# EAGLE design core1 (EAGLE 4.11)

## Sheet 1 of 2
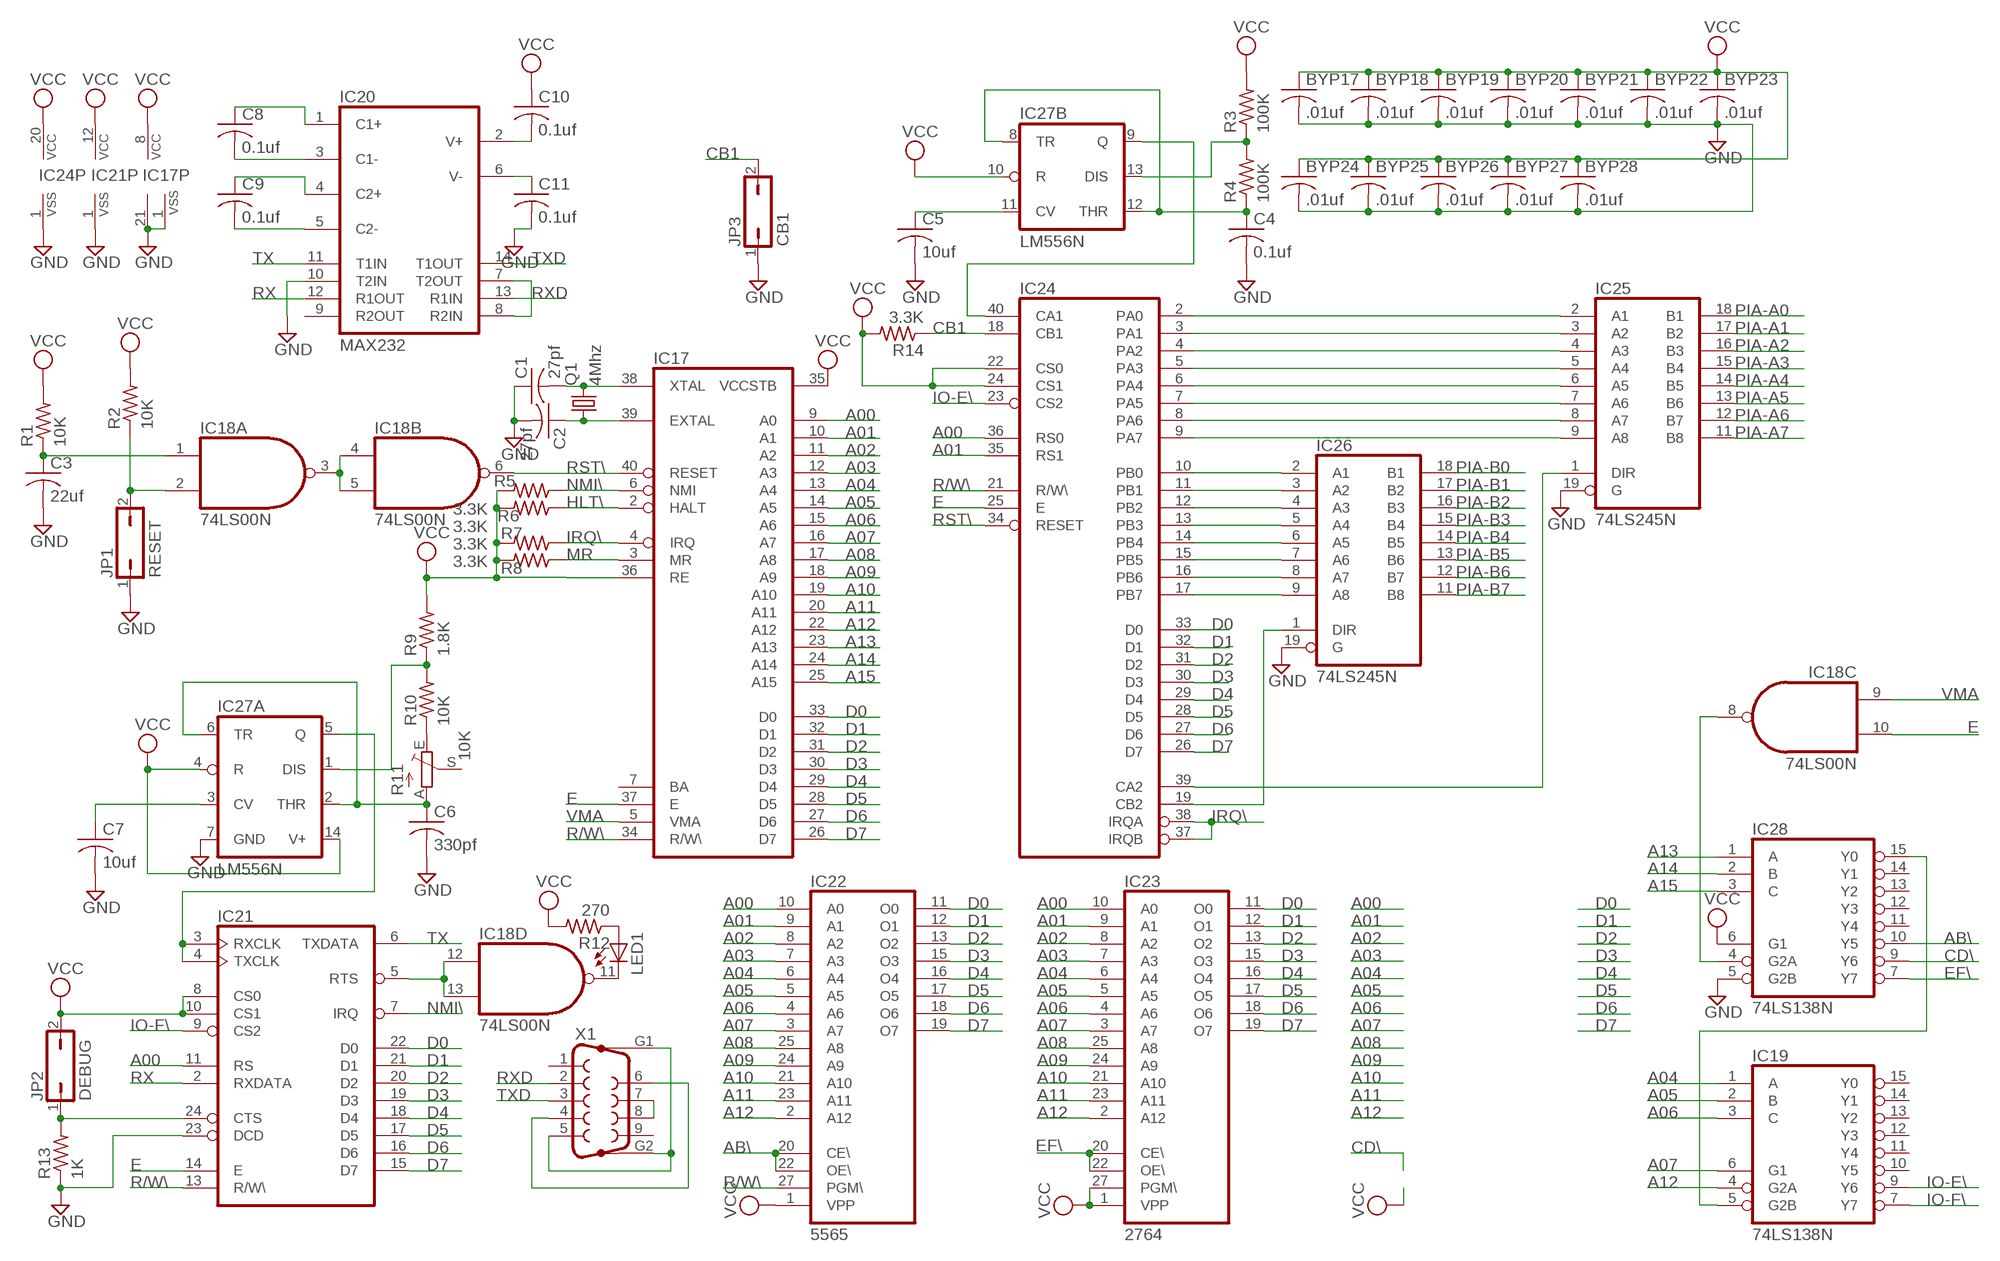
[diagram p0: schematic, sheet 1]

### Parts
BYP17  .01uf  C-US050-025X075  [C050-025X075]
BYP18  .01uf  C-US050-025X075  [C050-025X075]
BYP19  .01uf  C-US050-025X075  [C050-025X075]
BYP20  .01uf  C-US050-025X075  [C050-025X075]
BYP21  .01uf  C-US050-025X075  [C050-025X075]
BYP22  .01uf  C-US050-025X075  [C050-025X075]
BYP23  .01uf  C-US050-025X075  [C050-025X075]
BYP24  .01uf  C-US050-025X075  [C050-025X075]
BYP25  .01uf  C-US050-025X075  [C050-025X075]
BYP26  .01uf  C-US050-025X075  [C050-025X075]
BYP27  .01uf  C-US050-025X075  [C050-025X075]
BYP28  .01uf  C-US050-025X075  [C050-025X075]
C1  27pf  C-US050-025X075  [C050-025X075]
C2  27pf  C-US050-025X075  [C050-025X075]
C3  22uf  C-US102-043X133  [C102-043X133]
C4  0.1uf  C-US050-025X075  [C050-025X075]
C5  10uf  C-US050-025X075  [C050-025X075]
C6  330pf  C-US050-025X075  [C050-025X075]
C7  10uf  C-US050-025X075  [C050-025X075]
C8  0.1uf  C-US050-025X075  [C050-025X075]
C9  0.1uf  C-US050-025X075  [C050-025X075]
C10  0.1uf  C-US050-025X075  [C050-025X075]
C11  0.1uf  C-US050-025X075  [C050-025X075]
IC17  6802  [DIL40]
IC18  74LS00N  [DIL14]
IC19  74LS138N  [DIL16]
IC20  MAX232  [DIL16]
IC21  6850  [DIL24]
IC22  5565  2764  [DIL28]
IC23  2764  [DIL28]
IC24  6821  [DIL40]
IC25  74LS245N  [DIL20]
IC26  74LS245N  [DIL20]
IC27  LM556N  [DIL14]
IC28  74LS138N  [DIL16]
JP1  RESET  JP1Q  [JP1]
JP2  DEBUG  JP1Q  [JP1]
JP3  CB1  JP1Q  [JP1]
LED1  LED3MM  [LED3MM]
Q1  4Mhz  CRYTALHC18U-V  [HC18U-V]
R1  10K  R-US_0207/7  [0207/7]
R2  10K  R-US_0207/7  [0207/7]
R3  100K  R-US_0207/7  [0207/7]
R4  100K  R-US_0207/7  [0207/7]
R5  3.3K  R-US_0207/7  [0207/7]
R6  3.3K  R-US_0207/7  [0207/7]
R7  3.3K  R-US_0207/7  [0207/7]
R8  3.3K  R-US_0207/7  [0207/7]
R9  1.8K  R-US_0207/7  [0207/7]
R10  10K  R-US_0207/7  [0207/7]
R11  10K  TRIM_EU-B90P  [SP19L]
R12  270  R-US_0207/7  [0207/7]
R13  1K  R-US_0207/7  [0207/7]
R14  3.3K  R-US_0207/7  [0207/7]
X1  F09HP  [F09HP]

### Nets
A00: IC17.9(A0) IC21.11(RS) IC22.10(A0) IC23.10(A0) IC24.36(RS0)
A01: IC17.10(A1) IC22.9(A1) IC23.9(A1) IC24.35(RS1)
A02: IC17.11(A2) IC22.8(A2) IC23.8(A2)
A03: IC17.12(A3) IC22.7(A3) IC23.7(A3)
A04: IC17.13(A4) IC19.1(A) IC22.6(A4) IC23.6(A4)
A05: IC17.14(A5) IC19.2(B) IC22.5(A5) IC23.5(A5)
A06: IC17.15(A6) IC19.3(C) IC22.4(A6) IC23.4(A6)
A07: IC17.16(A7) IC19.6(G1) IC22.3(A7) IC23.3(A7)
A08: IC17.17(A8) IC22.25(A8) IC23.25(A8)
A09: IC17.18(A9) IC22.24(A9) IC23.24(A9)
A10: IC17.19(A10) IC22.21(A10) IC23.21(A10)
A11: IC17.20(A11) IC22.23(A11) IC23.23(A11)
A12: IC17.22(A12) IC19.4(G2A) IC22.2(A12) IC23.2(A12)
A13: IC17.23(A13) IC28.1(A)
A14: IC17.24(A14) IC28.2(B)
A15: IC17.25(A15) IC28.3(C)
AB\: IC22.20(CE\) IC22.22(OE\) IC28.10(Y5)
CB1: IC24.18(CB1) JP3.2 R14.1
CD\: IC28.9(Y6)
D0: IC17.33(D0) IC21.22(D0) IC22.11(O0) IC23.11(O0) IC24.33(D0)
D1: IC17.32(D1) IC21.21(D1) IC22.12(O1) IC23.12(O1) IC24.32(D1)
D2: IC17.31(D2) IC21.20(D2) IC22.13(O2) IC23.13(O2) IC24.31(D2)
D3: IC17.30(D3) IC21.19(D3) IC22.15(O3) IC23.15(O3) IC24.30(D3)
D4: IC17.29(D4) IC21.18(D4) IC22.16(O4) IC23.16(O4) IC24.29(D4)
D5: IC17.28(D5) IC21.17(D5) IC22.17(O5) IC23.17(O5) IC24.28(D5)
D6: IC17.27(D6) IC21.16(D6) IC22.18(O6) IC23.18(O6) IC24.27(D6)
D7: IC17.26(D7) IC21.15(D7) IC22.19(O7) IC23.19(O7) IC24.26(D7)
E: IC17.37(E) IC18.10(C:I1) IC21.14(E) IC24.25(E)
EF\: IC23.20(CE\) IC23.22(OE\) IC28.7(Y7)
GND [Power]: BYP17.2 BYP18.2 BYP19.2 BYP20.2 BYP21.2 BYP22.2 BYP23.2 BYP24.2 BYP25.2 BYP26.2 BYP27.2 BYP28.2 C1.1 C2.2 C3.2 C4.2 C5.2 C6.2 C7.2 C11.2 IC17.1(VSS) IC17.21(VSS) IC20.10(T2IN) IC21.1(VSS) IC21.23(DCD) IC24.1(VSS) IC25.19(G) IC26.19(G) IC27.7(A:GND) IC28.5(G2B) JP1.1 JP3.1 R13.1 ; also sheet 2
HLT\: IC17.2(HALT) R5.1
IO-E\: IC19.9(Y6) IC24.23(CS2)
IO-F\: IC19.7(Y7) IC21.9(CS2)
IRQ\: IC17.4(IRQ) IC24.37(IRQB) IC24.38(IRQA) R7.1
MR: IC17.3(MR) R8.1
N$3: C2.1 IC17.39(EXTAL) Q1.1
N$4: C1.2 IC17.38(XTAL) Q1.2
N$5: IC24.2(PA0) IC25.2(A1)
N$6: IC18.3(A:O) IC18.4(B:I0) IC18.5(B:I1)
N$21: C3.1 IC18.1(A:I0) R1.1
N$22: IC18.2(A:I1) JP1.2 R2.1
N$23: IC21.3(RXCLK) IC21.4(TXCLK) IC27.5(A:Q)
N$24: IC24.10(PB0) IC26.2(A1)
N$25: IC24.11(PB1) IC26.3(A2)
N$27: C6.1 IC27.2(A:THR) IC27.6(A:TR) R11.A
N$28: IC27.1(A:DIS) R9.1 R10.2
N$94: IC24.12(PB2) IC26.4(A3)
N$124: IC24.13(PB3) IC26.5(A4)
N$125: IC24.14(PB4) IC26.6(A5)
N$126: IC24.15(PB5) IC26.7(A6)
N$127: IC24.16(PB6) IC26.8(A7)
N$128: IC24.17(PB7) IC26.9(A8)
N$129: IC24.3(PA1) IC25.3(A2)
N$130: IC24.4(PA2) IC25.4(A3)
N$131: IC24.5(PA3) IC25.5(A4)
N$132: IC24.6(PA4) IC25.6(A5)
N$133: IC24.7(PA5) IC25.7(A6)
N$134: IC24.8(PA6) IC25.8(A7)
N$135: IC24.9(PA7) IC25.9(A8)
N$136: IC24.19(CB2) IC26.1(DIR)
N$137: IC24.39(CA2) IC25.1(DIR)
N$138: IC24.40(CA1) IC27.9(B:Q)
N$140: C4.1 IC27.8(B:TR) IC27.12(B:THR) R4.1
N$141: IC27.13(B:DIS) R3.1 R4.2
N$142: C5.1 IC27.11(B:CV)
N$143: R10.1 R11.E
N$144: X1.4 X1.6
N$145: X1.7 X1.8
N$146: X1.5 X1.G1 X1.G2
N$147: IC18.12(D:I0) IC18.13(D:I1) IC21.5(RTS)
N$148: IC18.11(D:O) LED1.K(C)
N$149: LED1.A R12.1
N$150: IC21.24(CTS) JP2.1 R13.2
N$151: IC18.8(C:O) IC28.4(G2A)
N$152: IC19.5(G2B) IC28.15(Y0)
N$153: IC20.7(T2OUT) IC20.8(R2IN)
N$154: C7.1 IC27.3(A:CV)
N$155: C9.2 IC20.5(C2-)
N$156: C9.1 IC20.4(C2+)
N$157: C8.2 IC20.3(C1-)
N$158: C8.1 IC20.1(C1+)
N$159: C11.1 IC20.6(V-)
N$160: C10.2 IC20.2(V+)
NMI\: IC17.6(NMI) IC21.7(IRQ) R6.1
PIA-A0: IC25.18(B1) ; also sheet 2
PIA-A1: IC25.17(B2) ; also sheet 2
PIA-A2: IC25.16(B3) ; also sheet 2
PIA-A3: IC25.15(B4) ; also sheet 2
PIA-A4: IC25.14(B5) ; also sheet 2
PIA-A5: IC25.13(B6) ; also sheet 2
PIA-A6: IC25.12(B7) ; also sheet 2
PIA-A7: IC25.11(B8) ; also sheet 2
PIA-B0: IC26.18(B1) ; also sheet 2
PIA-B1: IC26.17(B2) ; also sheet 2
PIA-B2: IC26.16(B3) ; also sheet 2
PIA-B3: IC26.15(B4) ; also sheet 2
PIA-B4: IC26.14(B5) ; also sheet 2
PIA-B5: IC26.13(B6) ; also sheet 2
PIA-B6: IC26.12(B7) ; also sheet 2
PIA-B7: IC26.11(B8) ; also sheet 2
R/W\: IC17.34(R/W\) IC21.13(R/W\) IC22.27(PGM\) IC24.21(R/W\)
RST\: IC17.40(RESET) IC18.6(B:O) IC24.34(RESET)
RX: IC20.12(R1OUT) IC21.2(RXDATA)
RXD: IC20.13(R1IN) X1.2
TX: IC20.11(T1IN) IC21.6(TXDATA)
TXD: IC20.14(T1OUT) X1.3
VCC [Power]: BYP17.1 BYP18.1 BYP19.1 BYP20.1 BYP21.1 BYP22.1 BYP23.1 BYP24.1 BYP25.1 BYP26.1 BYP27.1 BYP28.1 C10.1 IC17.8(VCC) IC17.35(VCCSTB) IC17.36(RE) IC21.8(CS0) IC21.10(CS1) IC21.12(VCC) IC22.1(VPP) IC23.1(VPP) IC23.27(PGM\) IC24.20(VCC) IC24.22(CS0) IC24.24(CS1) IC27.4(A:R) IC27.10(B:R) IC27.14(A:V+) IC28.6(G1) JP2.2 R1.2 R2.2 R3.2 R5.2 R6.2 R7.2 R8.2 R9.2 R12.2 R14.2 ; also sheet 2
VMA: IC17.5(VMA) IC18.9(C:I0)
Unconnected: IC17.7(BA) IC19.10(Y5) IC19.11(Y4) IC19.12(Y3) IC19.13(Y2) IC19.14(Y1) IC19.15(Y0) IC20.9(R2OUT) IC28.11(Y4) IC28.12(Y3) IC28.13(Y2) IC28.14(Y1) R11.S X1.1 X1.9

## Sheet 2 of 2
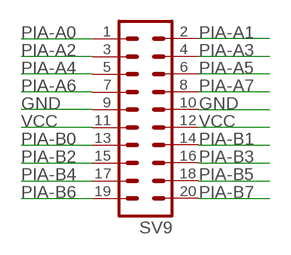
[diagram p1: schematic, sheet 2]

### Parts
SV9  MA10-2  [MA10-2]

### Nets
GND [Power]: SV9.9 SV9.10 ; also sheet 1
PIA-A0: SV9.1 ; also sheet 1
PIA-A1: SV9.2 ; also sheet 1
PIA-A2: SV9.3 ; also sheet 1
PIA-A3: SV9.4 ; also sheet 1
PIA-A4: SV9.5 ; also sheet 1
PIA-A5: SV9.6 ; also sheet 1
PIA-A6: SV9.7 ; also sheet 1
PIA-A7: SV9.8 ; also sheet 1
PIA-B0: SV9.13 ; also sheet 1
PIA-B1: SV9.14 ; also sheet 1
PIA-B2: SV9.15 ; also sheet 1
PIA-B3: SV9.16 ; also sheet 1
PIA-B4: SV9.17 ; also sheet 1
PIA-B5: SV9.18 ; also sheet 1
PIA-B6: SV9.19 ; also sheet 1
PIA-B7: SV9.20 ; also sheet 1
VCC [Power]: SV9.11 SV9.12 ; also sheet 1

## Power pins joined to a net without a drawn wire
GND: IC18.7(P:GND) IC19.8(GND) IC20.15(GND) IC22.14(GND) IC23.14(GND) IC25.10(GND) IC26.10(GND) IC28.8(GND)
VCC: IC18.14(P:VCC) IC19.16(VCC) IC20.16(VCC) IC22.28(VCC) IC23.28(VCC) IC25.20(VCC) IC26.20(VCC) IC28.16(VCC)

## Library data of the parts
BYP17-BYP28 C1-C11 = rcl:C-US: CAPACITOR, American symbol
IC17 = micro-motorola:6802: MICROCONTROLLER/MEMORY DEVICE
IC18 = 74xx-us:74*00: Quad 2-input NAND gate
IC19 IC28 = 74xx-us:74*138: 3-line to 8-line DECODER/DEMULTIPLEXER
IC20 = maxim:MAX232: RS232 TRANSEIVER
IC21 = micro-motorola:6850: MICROCONTROLLER/MEMORY DEVICE
IC22 IC23 = memory:2764: MEMORY
IC24 = micro-motorola:6821: MICROCONTROLLER/MEMORY DEVICE
IC25 IC26 = 74xx-us:74*245: Octal BUS TRANSCEIVER, 3-state
IC27 = linear:*556: Dual TIMER
JP1-JP3 = jumper:JP1Q: JUMPER
LED1 = led:LED: LED
Q1 = crystal:CRYTAL: CRYSTAL
R1-R10 R12-R14 = rcl:R-US_: RESISTOR, American symbol
R11 = pot:TRIM_EU-: POTENTIOMETER
SV9 = con-lstb:MA10-2: PIN HEADER
X1 = con-subd:F09HP: SUB-D

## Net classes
1 Power: width 0.508 mm, drill 0.254 mm, clearance 0.254 mm

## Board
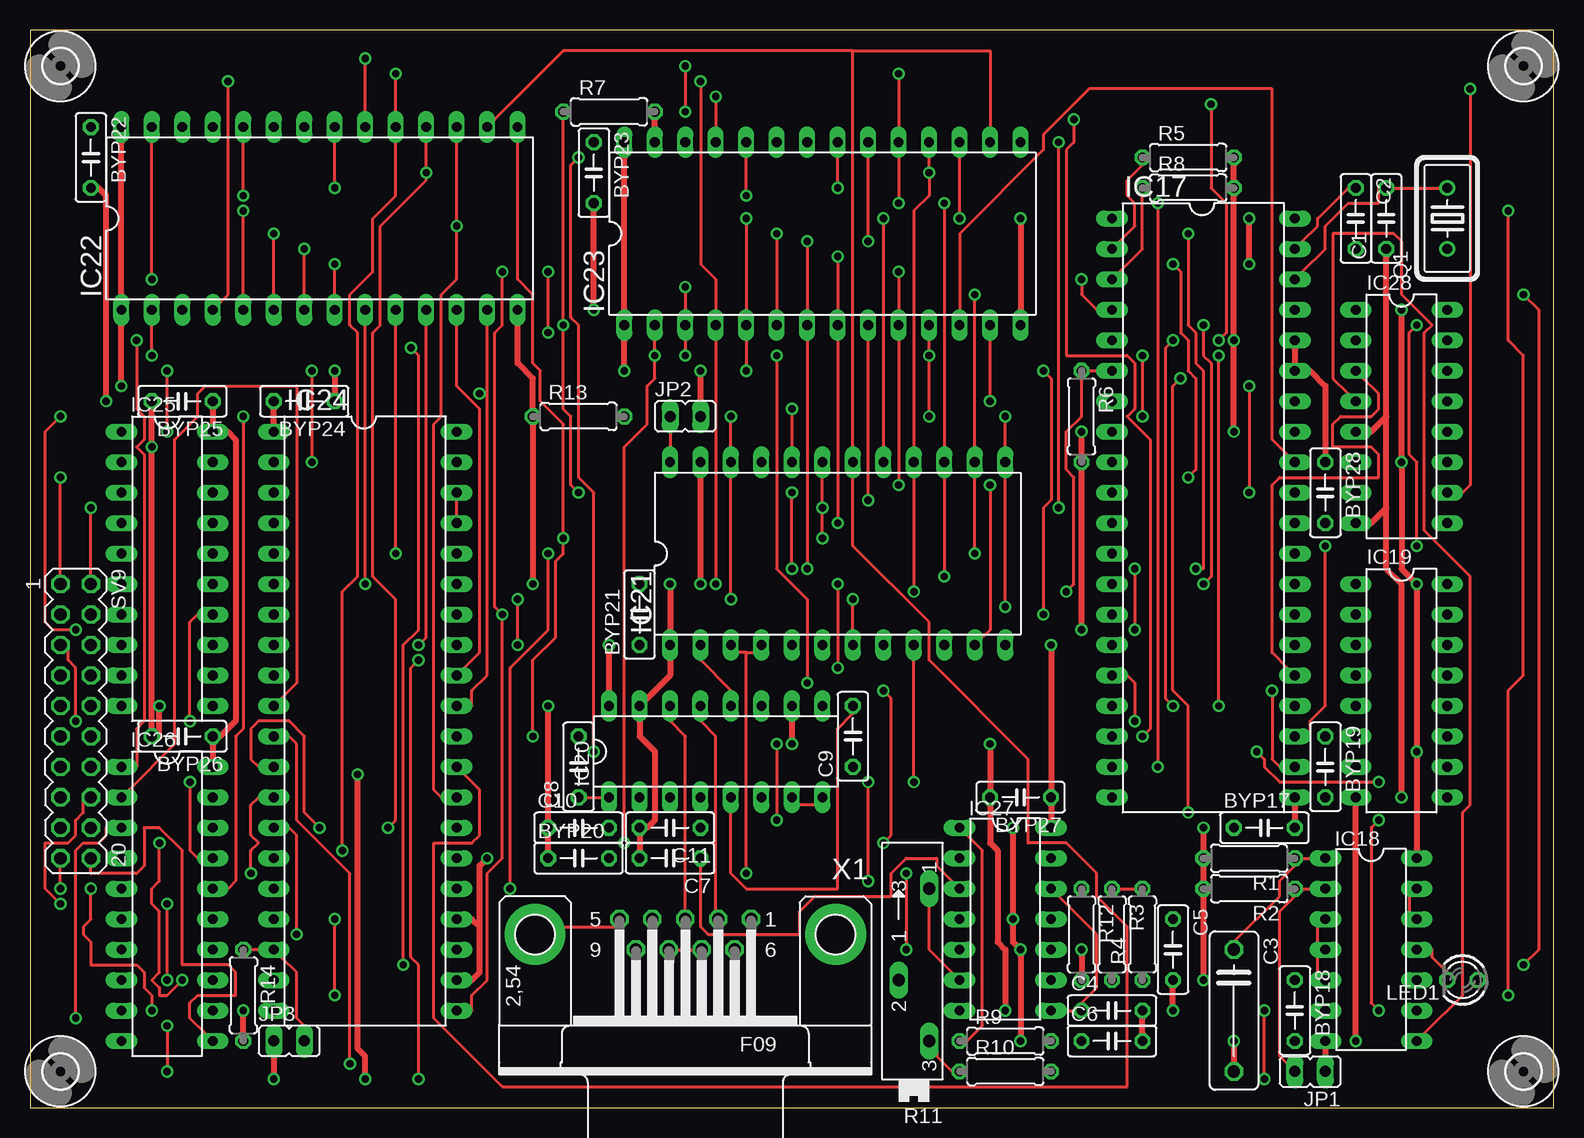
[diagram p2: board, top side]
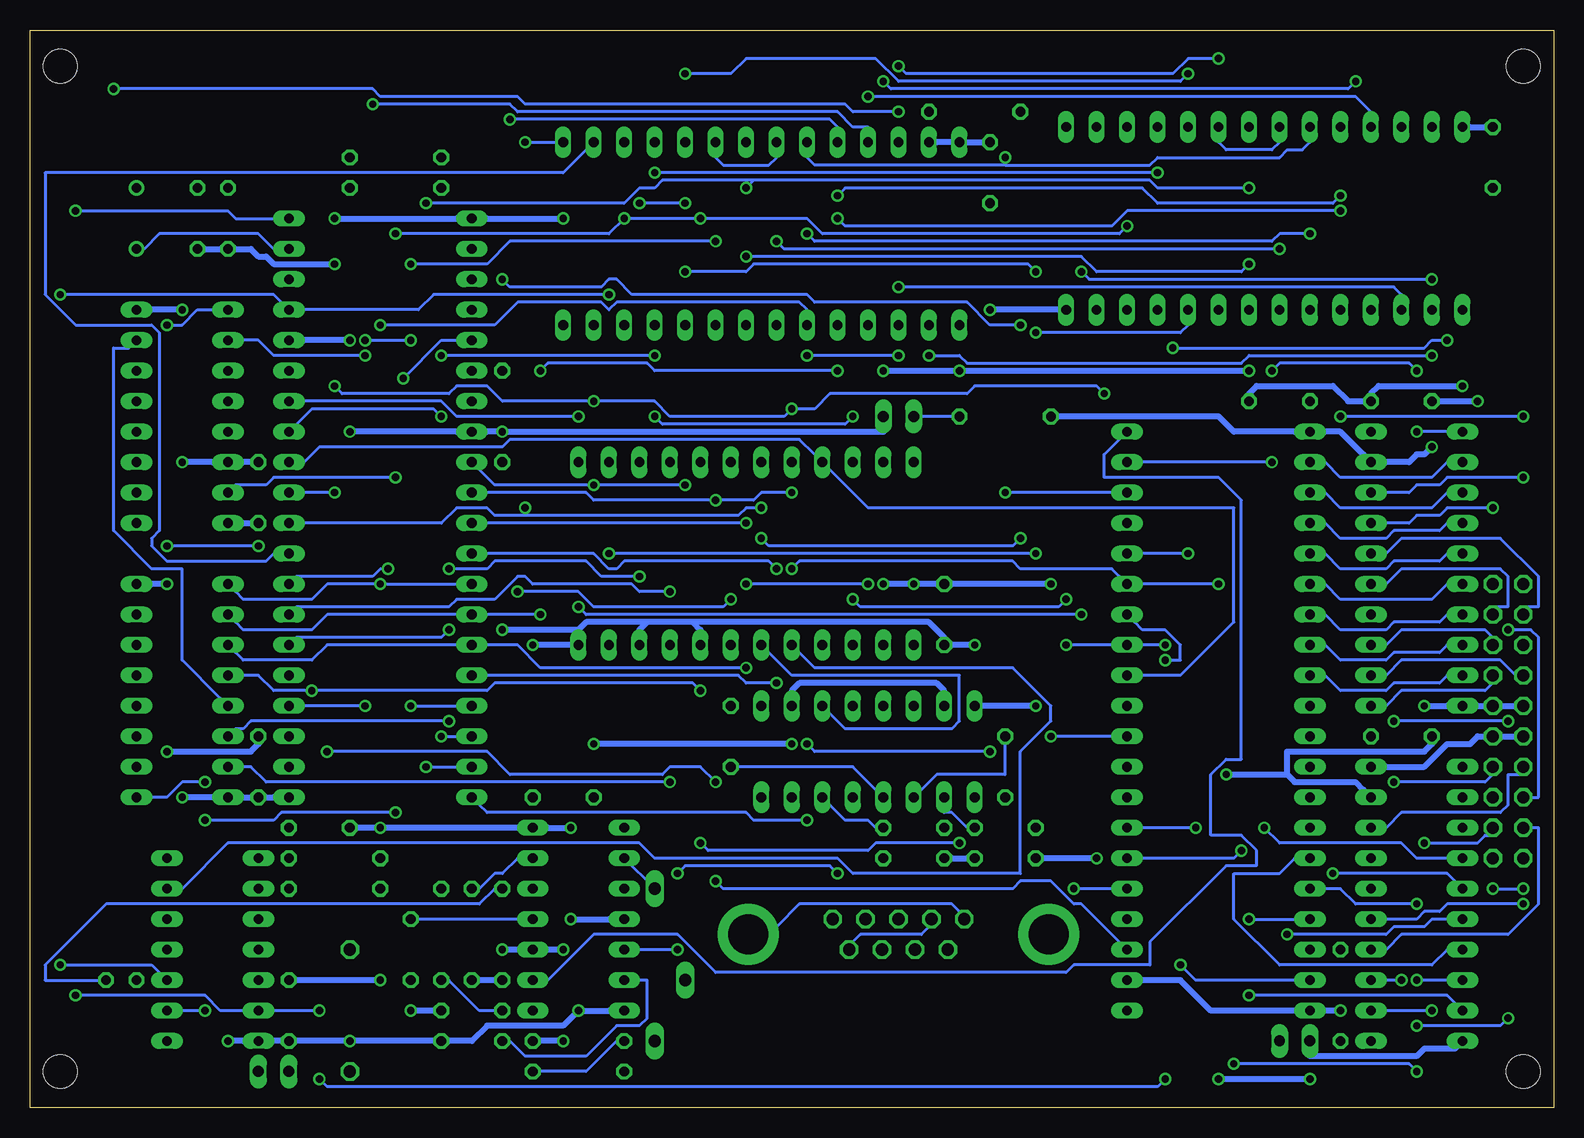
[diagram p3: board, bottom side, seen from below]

Size 126.98 x 89.84 mm. Coordinates in mm from the lower left corner, seen from the top.
Outline: 0,0 126.98,0 126.98,89.84 0,89.84 0,0
Copper layers (1*16): Top 0.035mm / dielectric 1.5mm / Bottom 0.035mm
Design rules "default": minimum track width 10mil, minimum drill 24mil, track to track 8mil, track to pad 8mil, pad to pad 8mil, via to via 8mil, smd to smd 8mil, copper to edge 40mil, drill to drill 8mil, minimum pad ring 10mil, minimum via ring 8mil, stop-mask expansion 4mil, vias tented up to drill 0mil, thermal gap 10mil

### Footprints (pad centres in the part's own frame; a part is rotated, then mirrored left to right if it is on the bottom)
C050-025X075 = drill 0.813 octagon: 1 -2.54,0; 2 2.54,0
C102-043X133 = drill 1.016 octagon: 1 -5.08,0; 2 5.08,0
DIL40 = drill 0.813 long: 1 -24.13,-7.62; 2 -21.59,-7.62; 3 -19.05,-7.62; 4 -16.51,-7.62; 5 -13.97,-7.62; 6 -11.43,-7.62; 7 -8.89,-7.62; 8 -6.35,-7.62; 9 -3.81,-7.62; 10 -1.27,-7.62; 11 1.27,-7.62; 12 3.81,-7.62; 13 6.35,-7.62; 14 8.89,-7.62; 15 11.43,-7.62; 16 13.97,-7.62; 17 16.51,-7.62; 18 19.05,-7.62; 19 21.59,-7.62; 20 24.13,-7.62; 21 24.13,7.62; 22 21.59,7.62; 23 19.05,7.62; 24 16.51,7.62; 25 13.97,7.62; 26 11.43,7.62; 27 8.89,7.62; 28 6.35,7.62; 29 3.81,7.62; 30 1.27,7.62; 31 -1.27,7.62; 32 -3.81,7.62; 33 -6.35,7.62; 34 -8.89,7.62; 35 -11.43,7.62; 36 -13.97,7.62; 37 -16.51,7.62; 38 -19.05,7.62; 39 -21.59,7.62; 40 -24.13,7.62
DIL14 = drill 0.813 long: 1 -7.62,-3.81; 2 -5.08,-3.81; 3 -2.54,-3.81; 4 0,-3.81; 5 2.54,-3.81; 6 5.08,-3.81; 7 7.62,-3.81; 8 7.62,3.81; 9 5.08,3.81; 10 2.54,3.81; 11 0,3.81; 12 -2.54,3.81; 13 -5.08,3.81; 14 -7.62,3.81
DIL16 = drill 0.813 long: 1 -8.89,-3.81; 2 -6.35,-3.81; 3 -3.81,-3.81; 4 -1.27,-3.81; 5 1.27,-3.81; 6 3.81,-3.81; 7 6.35,-3.81; 8 8.89,-3.81; 9 8.89,3.81; 10 6.35,3.81; 11 3.81,3.81; 12 1.27,3.81; 13 -1.27,3.81; 14 -3.81,3.81; 15 -6.35,3.81; 16 -8.89,3.81
DIL24 = drill 0.813 long: 1 -13.97,-7.62; 2 -11.43,-7.62; 3 -8.89,-7.62; 4 -6.35,-7.62; 5 -3.81,-7.62; 6 -1.27,-7.62; 7 1.27,-7.62; 8 3.81,-7.62; 9 6.35,-7.62; 10 8.89,-7.62; 11 11.43,-7.62; 12 13.97,-7.62; 13 13.97,7.62; 14 11.43,7.62; 15 8.89,7.62; 16 6.35,7.62; 17 3.81,7.62; 18 1.27,7.62; 19 -1.27,7.62; 20 -3.81,7.62; 21 -6.35,7.62; 22 -8.89,7.62; 23 -11.43,7.62; 24 -13.97,7.62
DIL28 = drill 0.813 long: 1 -16.51,-7.62; 2 -13.97,-7.62; 3 -11.43,-7.62; 4 -8.89,-7.62; 5 -6.35,-7.62; 6 -3.81,-7.62; 7 -1.27,-7.62; 8 1.27,-7.62; 9 3.81,-7.62; 10 6.35,-7.62; 11 8.89,-7.62; 12 11.43,-7.62; 13 13.97,-7.62; 14 16.51,-7.62; 15 16.51,7.62; 16 13.97,7.62; 17 11.43,7.62; 18 8.89,7.62; 19 6.35,7.62; 20 3.81,7.62; 21 1.27,7.62; 22 -1.27,7.62; 23 -3.81,7.62; 24 -6.35,7.62; 25 -8.89,7.62; 26 -11.43,7.62; 27 -13.97,7.62; 28 -16.51,7.62
DIL20 = drill 0.813 long: 1 -11.43,-3.81; 2 -8.89,-3.81; 3 -6.35,-3.81; 4 -3.81,-3.81; 5 -1.27,-3.81; 6 1.27,-3.81; 7 3.81,-3.81; 8 6.35,-3.81; 9 8.89,-3.81; 10 11.43,-3.81; 11 11.43,3.81; 12 8.89,3.81; 13 6.35,3.81; 14 3.81,3.81; 15 1.27,3.81; 16 -1.27,3.81; 17 -3.81,3.81; 18 -6.35,3.81; 19 -8.89,3.81; 20 -11.43,3.81
JP1 = drill 0.914 long: 1 0,-1.27; 2 0,1.27
LED3MM = drill 0.813 octagon: A -1.27,0; K 1.27,0
HC18U-V = drill 0.813 round: 1 -2.54,0; 2 2.54,0
0207/7 = drill 0.813 octagon: 1 -3.81,0; 2 3.81,0
SP19L = drill 1.016 long: A 5.715,-1.27; E -6.985,-1.27; S -1.905,1.27
MA10-2 = drill 1.016 octagon: 1 -11.43,-1.27; 2 -11.43,1.27; 3 -8.89,-1.27; 4 -8.89,1.27; 5 -6.35,-1.27; 6 -6.35,1.27; 7 -3.81,-1.27; 8 -3.81,1.27; 9 -1.27,-1.27; 10 -1.27,1.27; 11 1.27,-1.27; 12 1.27,1.27; 13 3.81,-1.27; 14 3.81,1.27; 15 6.35,-1.27; 16 6.35,1.27; 17 8.89,-1.27; 18 8.89,1.27; 19 11.43,-1.27; 20 11.43,1.27
2,8 = hole 2.8: 0,0
F09HP = drill 1.016 octagon: 1 -5.486,-1.27; 2 -2.743,-1.27; 3 0,-1.27; 4 2.743,-1.27; 5 5.486,-1.27; 6 -4.115,1.27; 7 -1.372,1.27; 8 1.372,1.27; 9 4.115,1.27 | drill 3.302 pad 5.08 round: G1 -12.522,0; G2 12.522,0

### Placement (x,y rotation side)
BYP17  102.87,23.33 0 top
BYP18  105.41,8.09 270 top
BYP19  107.95,28.41 270 top
BYP20  45.71,20.79 0 top
BYP21  50.79,41.11 90 top
BYP22  5.08,79.21 270 top
BYP23  46.98,77.94 270 top
BYP24  22.86,58.89 180 top
BYP25  12.69,58.89 180 top
BYP26  12.69,30.95 180 top
BYP27  82.55,25.87 180 top
BYP28  107.95,51.27 270 top
C1  113.03,74.13 90 top
C2  110.48,74.13 270 top
C3  100.33,8.09 270 top
C4  90.17,8.09 0 top
C5  95.25,13.17 270 top
C6  90.17,5.55 0 top
C7  53.34,20.79 180 top
C8  45.71,28.41 90 top
C9  68.58,30.95 90 top
C10  45.71,23.33 0 top
C11  53.34,23.33 180 top
IC17  97.79,50 270 top
IC18  111.76,13.17 270 top
IC19  114.3,34.76 270 top
IC20  57.14,29.68 0 top
IC21  67.31,46.19 0 top
IC22  24.12,74.13 0 top
IC23  66.04,72.86 0 top
IC24  27.94,32.22 270 top
IC25  11.42,44.92 270 top
IC26  11.42,16.98 270 top
IC27  81.28,15.71 270 top
IC28  114.3,57.62 270 top
JP1  106.68,3.01 90 top
JP2  54.6,57.62 270 top
JP3  21.59,5.55 270 top
LED1  119.38,10.63 180 top
Q1  118.11,74.13 90 top
R1  101.59,20.79 180 top
R2  101.59,18.25 180 top
R3  90.17,14.44 270 top
R4  92.7,14.44 90 top
R5  96.52,79.21 0 top
R6  87.62,57.62 270 top
R7  48.25,83.02 0 top
R8  96.52,76.67 0 top
R9  81.28,5.55 0 top
R10  81.28,3.01 0 top
R11  73.66,12.54 90 top
R12  87.62,14.44 270 top
R13  45.71,57.62 0 top
R14  17.78,9.36 270 top
SV9  3.81,32.22 270 top
U$3  [2,8]  2.54,86.83 0 top
U$4  [2,8]  2.54,3.01 0 top
U$5  [2,8]  124.45,86.83 0 top
U$6  [2,8]  124.45,3.01 0 top
X1  54.6,14.44 180 top

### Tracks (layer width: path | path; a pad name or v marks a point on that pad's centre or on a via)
A00  (via drill 0.61)
  Top 0.254: v30.48,46.19 30.48,65.24 IC22.10 | v80.01,51.91 80.01,39.84 79.37,39.2 IC21.11 | v72.39,51.91 72.39,63.97 IC23.10 72.39,66.51 v72.39,69.69 | v43.17,64.61 v43.17,69.69
  Bottom 0.254: v30.48,46.19 34.28,46.19 IC24.36 | IC17.9 89.53,53.17 88.26,51.91 v80.01,51.91 v72.39,51.91 | v43.17,64.61 31.11,64.61 30.48,65.24 IC22.10 | v43.17,69.69 43.81,70.32 66.67,70.32 67.31,69.69 v72.39,69.69
A01  (via drill 0.61)
  Top 0.254: v27.94,43.65 27.94,65.24 IC22.9 | v69.84,50.63 69.84,63.97 IC23.9 | v63.49,44.92 v63.49,51.27
  Bottom 0.254: v27.94,43.65 34.28,43.65 IC24.35 36.19,44.28 36.82,44.92 44.45,44.92 45.08,45.55 62.86,45.55 v63.49,44.92 | IC17.10 88.9,51.27 80.64,51.27 80.01,50.63 v69.84,50.63 66.67,50.63 66.04,51.27 v63.49,51.27
A02  (via drill 0.61)
  Top 0.254: v25.39,70.32 25.39,67.78 IC22.8 | v67.31,70.95 67.31,66.51 IC23.8 67.31,63.97 v67.31,48.73
  Bottom 0.254: v25.39,70.32 26.03,69.69 38.09,69.69 39.36,70.95 v67.31,70.95 | v67.31,48.73 88.9,48.73 IC17.11
A03  (via drill 0.61)
  Top 0.254: v22.86,71.59 22.86,67.78 IC22.7 | v64.77,72.22 64.77,66.51 IC23.7 64.77,63.97 v64.77,44.92
  Bottom 0.254: v22.86,71.59 64.13,71.59 v64.77,72.22 | v64.77,44.92 65.4,45.55 77.47,45.55 78.1,44.92 78.73,44.92 80.01,46.19 88.9,46.19 IC17.12
A04  (via drill 0.61)
  Top 0.254: v20.32,72.86 20.32,67.78 IC22.6 | v62.22,72.86 62.22,66.51 IC23.6 | v97.79,43.65 98.42,44.28 98.42,62.06 97.79,62.7 v97.79,65.24
  Bottom 0.254: IC19.1 109.85,43.02 109.22,42.38 103.5,42.38 102.23,43.65 v97.79,43.65 91.44,43.65 IC17.13 | v20.32,72.86 22.86,72.86 23.49,72.22 61.59,72.22 v62.22,72.86 | v97.79,65.24 88.26,65.24 86.36,67.14 79.37,67.14 78.73,66.51 78.1,67.14 62.86,67.14 62.22,66.51 IC23.6
A05  (via drill 0.61)
  Top 0.254: v17.78,74.77 17.78,67.78 IC22.5 | v59.68,74.13 59.68,66.51 IC23.5 59.68,63.97 v59.68,61.43 | v84.45,41.11 84.45,50 85.09,50.63 85.09,60.8 v84.45,61.43
  Bottom 0.254: IC19.2 109.85,40.48 109.22,39.84 103.5,39.84 102.23,41.11 91.44,41.11 IC17.14 88.9,41.11 v84.45,41.11 | v17.78,74.77 35.55,74.77 36.82,73.5 59.05,73.5 v59.68,74.13 | v84.45,61.43 83.81,62.06 75.56,62.06 74.93,61.43 v59.68,61.43
A06  (via drill 0.61)
  Top 0.254: v16.51,85.56 16.51,67.78 15.87,67.14 IC22.4 | v55.88,85.56 55.88,70.32 57.14,69.05 57.14,66.51 IC23.4 57.14,63.97 v57.14,43.65 | v67.31,43.65 v67.31,36.66
  Bottom 0.254: IC19.3 109.85,37.94 109.22,37.3 103.5,37.3 102.23,38.57 91.44,38.57 IC17.15 88.9,38.57 86.36,38.57 84.45,36.66 v67.31,36.66 | v16.51,85.56 17.14,84.92 55.24,84.92 v55.88,85.56 | v57.14,43.65 v67.31,43.65
A07  (via drill 0.61)
  Top 0.254: v92.07,32.22 92.07,35.39 91.44,36.03 IC17.16 | v54.6,68.41 54.6,66.51 IC23.3 54.6,63.97 v54.6,62.7 | v64.77,35.39 64.77,42.38 62.22,44.92 v62.22,62.7
  Bottom 0.254: v92.07,32.22 108.58,32.22 109.22,31.58 109.85,31.58 IC19.6 | v54.6,68.41 13.33,68.41 12.69,67.78 IC22.3 | v64.77,35.39 67.31,35.39 67.94,36.03 88.9,36.03 IC17.16 | v54.6,62.7 v62.22,62.7
A08  (via drill 0.61)
  Top 0.254: v57.14,84.29 57.14,81.75 IC23.25 | v95.25,33.49 94.61,34.12 94.61,63.34 v95.25,63.97 | v99.06,63.97 99.69,64.61 99.69,75.4 98.42,76.67 v98.42,83.66
  Bottom 0.254: v57.14,84.29 16.51,84.29 15.23,83.02 IC22.25 | v95.25,33.49 91.44,33.49 IC17.17 | v99.06,63.97 v95.25,63.97 | v98.42,83.66 86.99,83.66 86.36,83.02 59.68,83.02 58.41,81.75 57.14,81.75 IC23.25
A09  (via drill 0.61)
  Top 0.254: v17.78,76.03 17.78,80.48 IC22.24 | v59.68,76.03 59.68,79.21 IC23.24 | v92.7,30.95 93.34,31.58 93.34,55.71 91.44,57.62 92.07,58.25 92.07,62.06 91.44,62.7 86.36,62.7 86.36,79.84 86.99,80.48 v86.99,82.39
  Bottom 0.254: v17.78,76.03 18.41,75.4 33.02,75.4 34.28,76.67 59.05,76.67 v59.68,76.03 | v92.7,30.95 91.44,30.95 IC17.18 | v86.99,82.39 60.32,82.39 59.68,81.75 IC23.24
A10  (via drill 0.61)
  Top 0.254: v25.39,76.67 25.39,80.48 IC22.21 | v67.31,76.67 67.31,79.21 IC23.21 | v93.98,75.4 v93.98,28.41
  Bottom 0.254: v25.39,76.67 33.02,76.67 33.65,77.3 66.67,77.3 | 66.67,77.3 v67.31,76.67 | v93.98,28.41 91.44,28.41 IC17.19 | v93.98,75.4 77.47,75.4 76.2,76.67 74.93,76.67 74.29,77.3 66.67,77.3
A11  (via drill 0.61)
  Top 0.254: v62.22,30.31 v62.22,23.96 | v46.98,29.68 46.98,51.27 45.71,52.54 45.71,65.24 45.08,65.88 45.08,78.58 v45.71,79.21
  Bottom 0.254: 45.71,78.58 61.59,78.58 62.22,79.21 IC23.23 | 45.71,78.58 33.65,78.58 33.02,79.21 22.86,79.21 22.22,79.84 20.95,79.84 20.32,80.48 IC22.23 | v62.22,23.96 66.67,23.96 67.31,24.6 88.9,24.6 89.53,25.23 IC17.20 | v62.22,30.31 61.59,29.68 v46.98,29.68 | v45.71,79.21 45.71,78.58
A12  (via drill 0.61)
  Top 0.254: v103.5,34.76 103.5,29.04 104.14,28.41 IC17.22 | v10.15,62.7 10.15,65.24 IC22.2 | IC23.2 52.06,63.97 v52.06,62.7 52.06,60.8 51.43,60.16 51.43,56.98 49.52,55.08 v49.52,22.06 | v71.12,34.76 71.75,34.12 71.75,22.7 v71.12,22.06
  Bottom 0.254: IC19.4 109.22,36.03 107.95,36.03 106.68,34.76 v103.5,34.76 88.9,34.76 88.26,35.39 71.75,35.39 v71.12,34.76 | v10.15,62.7 25.39,62.7 26.03,62.06 48.89,62.06 49.52,62.7 v52.06,62.7 | v71.12,22.06 70.48,21.42 57.14,21.42 56.51,22.06 v49.52,22.06
A13  (via drill 0.61)
  Top 0.254: v107.95,46.82 107.95,33.49 106.68,32.22 106.68,30.95 IC17.23 | v115.56,46.82 115.56,53.81 114.93,54.45 114.93,64.61 v115.56,65.24
  Bottom 0.254: v107.95,46.82 v115.56,46.82 | v115.56,65.24 114.3,65.24 113.03,66.51 111.76,66.51 IC28.1
A14  (via drill 0.61)
  Top 0.254: v99.06,33.49 v99.06,62.7
  Bottom 0.254: v99.06,33.49 104.14,33.49 IC17.24 | v99.06,62.7 106.68,62.7 107.95,63.97 109.22,63.97 IC28.2
A15
  Top 0.254: IC17.25 104.77,36.66 103.5,37.94 103.5,51.91 104.14,52.54 112.39,52.54 112.39,54.45 111.76,55.08 108.58,55.08 108.58,56.98 109.22,57.62 111.76,57.62 112.39,58.25 112.39,59.52 111.12,60.8 IC28.3
AB\  (via drill 0.61)
  Top 0.254: v120.01,84.92 120.01,51.91 119.38,51.27 IC28.10 | v54.6,86.83 v54.6,83.02 | v27.94,87.47 27.94,83.02 IC22.20
  Bottom 0.254: IC22.20 27.94,80.48 27.3,79.84 23.49,79.84 22.86,80.48 IC22.22 | v120.01,84.92 98.42,84.92 97.79,84.29 86.36,84.29 85.72,83.66 59.05,83.66 58.41,83.02 v54.6,83.02 | v54.6,86.83 53.97,86.19 31.75,86.19 30.48,87.47 v27.94,87.47
CB1
  Top 0.254: R14.1 18.41,13.17 19.05,13.17 IC24.18 20.95,12.54 22.22,11.27 22.22,7.46 22.86,6.82 JP3.2
D0  (via drill 0.61)
  Top 0.254: v32.38,38.57 33.02,39.2 33.02,65.24 IC22.11 | v58.41,57.62 58.41,55.08 IC21.22 58.41,52.54 v58.41,42.38 | v74.93,57.62 v74.93,62.7 74.93,63.97 IC23.11 | v92.7,62.7 v92.7,57.62 | v40.63,38.57 v40.63,42.38
  Bottom 0.254: v32.38,38.57 34.28,38.57 IC24.33 36.82,38.57 v40.63,38.57 | v58.41,57.62 59.05,56.98 74.29,56.98 v74.93,57.62 | v92.7,57.62 93.34,58.25 103.5,58.25 104.77,56.98 IC17.33 | v74.93,62.7 v92.7,62.7 | v40.63,42.38 41.27,41.74 57.78,41.74 v58.41,42.38
D1
  Top 0.254: IC24.32 36.19,36.66 37.46,37.94 37.46,58.25 35.55,60.16 35.55,65.24 IC22.12 | IC23.12 77.47,66.51 77.47,72.86 84.45,79.84 84.45,81.11 88.26,84.92 103.5,84.92 103.5,55.71 104.77,54.45 IC17.32
  Bottom 0.254: IC17.32 104.14,53.81 102.87,55.08 87.62,55.08 86.99,55.71 62.86,55.71 61.59,54.45 IC21.21 60.32,53.17 57.14,50 26.67,50 26.67,40.48 31.11,36.03 34.28,36.03 IC24.32
D2  (via drill 0.61)
  Top 0.254: 38.09,59.52 38.09,65.24 IC22.13 | 38.09,59.52 38.09,36.03 36.82,34.76 36.82,33.49 IC24.31 | v63.49,58.25 63.49,55.08 IC21.20 | v80.01,58.89 80.01,63.97 IC23.13 | v101.59,60.16 v101.59,51.27 | 38.09,59.52 v37.46,59.52
  Bottom 0.254: v101.59,51.27 104.14,51.27 IC17.31 | v101.59,60.16 100.96,59.52 92.07,59.52 91.44,60.16 88.9,60.16 87.62,58.89 v80.01,58.89 74.93,58.89 73.66,57.62 64.13,57.62 v63.49,58.25 61.59,58.25 60.32,59.52 48.89,59.52 48.25,60.16 38.09,60.16 v37.46,59.52
D3  (via drill 0.61)
  Top 0.254: v41.9,30.95 41.9,37.3 43.81,39.2 43.81,45.55 44.45,46.19 v44.45,47.46 44.45,56.98 42.54,58.89 42.54,61.43 41.9,62.06 41.9,67.78 40.63,69.05 40.63,80.48 IC22.15 | v66.04,47.46 v66.04,50 66.04,52.54 IC21.19 | v85.72,50 v85.72,80.48
  Bottom 0.254: v41.9,30.95 36.82,30.95 IC24.30 | v44.45,47.46 45.08,46.82 65.4,46.82 v66.04,47.46 | 85.72,49.37 67.94,49.37 67.31,50 v66.04,50 | 85.72,49.37 88.26,49.37 88.9,50 91.44,50 92.7,48.73 104.14,48.73 IC17.30 | v85.72,80.48 83.18,80.48 IC23.15 | 85.72,49.37 v85.72,50
D4
  Top 0.254: IC24.29 36.19,27.77 37.46,26.5 37.46,22.7 36.82,22.06 33.65,22.06 33.65,7.46 39.36,1.74 91.44,1.74 91.44,15.08 88.9,17.61 88.9,19.52 86.36,22.06 83.18,22.06 83.18,29.04 74.93,37.3 74.93,40.48 68.58,46.82 68.58,52.54 IC21.18 68.58,55.08 68.58,88.1 | 68.58,88.1 80.01,88.1 80.01,81.75 IC23.16 | 68.58,88.1 44.45,88.1 38.73,82.39 IC22.16
  Bottom 0.254: IC17.29 106.68,46.19 107.31,45.55 115.56,45.55 116.84,46.82 116.84,47.46 116.2,48.09 116.2,64.61 116.84,65.24 123.19,65.24 125.73,67.78 125.73,77.94 82.55,77.94 80.64,79.84 IC23.16
D5  (via drill 0.61)
  Top 0.254: IC22.17 35.55,80.48 v35.55,73.5 35.55,69.05 34.28,67.78 34.28,57.62 33.65,56.98 33.65,26.5 34.28,25.87 IC24.28 | v71.12,74.13 71.12,55.08 IC21.17 | v77.47,74.13 77.47,79.21 IC23.17 | v97.15,44.92 97.79,44.92 97.79,61.43 97.15,62.06 97.15,64.61 96.52,65.24 v96.52,72.86
  Bottom 0.254: v97.15,44.92 97.79,44.92 98.42,44.28 104.77,44.28 IC17.28 | v96.52,72.86 78.73,72.86 v77.47,74.13 v71.12,74.13 62.22,74.13 60.95,72.86 36.19,72.86 v35.55,73.5
D6  (via drill 0.61)
  Top 0.254: v29.84,23.33 30.48,23.96 30.48,42.38 28.57,44.28 28.57,64.61 29.21,65.24 29.21,73.5 33.02,77.3 v33.02,77.94 33.02,80.48 IC22.18 | IC23.18 74.93,79.21 v74.93,77.94 74.93,76.03 73.66,74.77 73.66,55.08 IC21.16 73.66,52.54 v73.66,43.02
  Bottom 0.254: v29.84,23.33 34.28,23.33 IC24.27 | v73.66,43.02 76.2,43.02 76.83,43.65 85.09,43.65 85.72,44.28 86.36,44.28 88.26,42.38 91.44,42.38 92.07,41.74 104.77,41.74 IC17.27 | v33.02,77.94 v74.93,77.94
D7  (via drill 0.61)
  Top 0.254: v26.03,21.42 26.03,43.02 27.3,44.28 27.3,64.61 26.67,65.24 26.67,67.78 28.57,69.69 28.57,74.13 30.48,76.03 30.48,80.48 IC22.19 30.48,83.02 v30.48,86.19 | v76.2,75.4 76.2,55.08 IC21.15 76.2,52.54 v76.2,44.28 | v72.39,75.4 72.39,79.21 IC23.19 72.39,81.75 v72.39,86.19 | v92.07,44.92 v92.07,39.84
  Bottom 0.254: v26.03,21.42 26.67,20.79 34.28,20.79 IC24.26 | v72.39,75.4 v76.2,75.4 | v92.07,39.84 92.7,39.2 104.77,39.2 IC17.26 | v92.07,44.92 88.9,44.92 88.26,45.55 80.64,45.55 79.37,44.28 v76.2,44.28 | v30.48,86.19 31.11,85.56 54.6,85.56 56.51,87.47 67.31,87.47 68.58,86.19 v72.39,86.19
E  (via drill 0.61)
  Top 0.254: v124.45,11.9 125.73,13.17 125.73,66.51 v124.45,67.78 | v40,18.25 40,36.66 43.17,39.84 v43.17,46.19 | v78.73,46.19 78.73,52.54 IC21.14 78.73,55.08 v78.73,67.78
  Bottom 0.254: v124.45,11.9 116.84,11.9 116.2,11.27 IC18.10 | v124.45,67.78 106.68,67.78 106.04,67.14 IC17.37 104.14,66.51 94.61,66.51 93.34,67.78 v78.73,67.78 | v40,18.25 36.82,18.25 IC24.25 | v43.17,46.19 v78.73,46.19
EF\  (via drill 0.61)
  Top 0.254: v96.52,52.54 97.15,53.17 97.15,60.8 96.52,61.43 96.52,63.97 95.88,64.61 95.88,69.69 v95.25,70.32 | v69.84,72.22 69.84,79.21 IC23.20
  Bottom 0.254: IC23.20 69.84,79.21 69.21,78.58 65.4,78.58 64.77,79.21 IC23.22 | v96.52,52.54 106.68,52.54 107.31,51.91 109.85,51.91 IC28.7 | v95.25,70.32 88.9,70.32 86.99,72.22 v69.84,72.22
GND  (via drill 0.61)
  Top 0.508: v82.55,74.13 82.55,66.51 IC23.14 | 113.03,57.62 111.76,56.35 IC28.5 | 113.03,57.62 113.03,70.95 C1.1 | 113.03,50 111.76,48.73 IC28.8 | 113.03,50 113.03,57.62 | v101.59,70.32 v101.59,74.13 | v81.28,8.09 81.28,13.17 80.64,13.81 80.64,21.42 80.01,22.06 80.01,25.23 BYP27.2 80.01,26.5 v80.01,30.31 | BYP17.2 105.41,23.96 105.41,25.23 IC17.21 | C6.2 92.7,6.18 92.7,7.46 C4.2 | v95.25,8.09 95.25,10 C5.2 | JP1.1 107.95,4.28 107.95,4.92 IC18.7 | v100.33,5.55 100.33,3.64 C3.2 | v110.48,5.55 110.48,25.23 IC19.8 | 113.03,50 113.03,44.92 114.3,43.65 v114.3,25.87 | IC22.14 40.63,65.24 40.63,62.06 41.9,60.8 41.9,58.25 R13.1 41.9,56.98 v41.9,43.65 | v46.98,66.51 46.98,74.77 BYP23.2 | C7.2 50.79,21.42 50.79,22.7 C11.2 51.43,23.33 52.06,23.96 52.06,29.68 50.79,30.95 50.79,32.22 IC20.15 51.43,34.12 53.34,36.03 53.34,37.3 IC21.1 53.34,39.84 v53.34,43.65 | v55.88,43.65 55.88,52.54 IC21.23 | BYP25.2 10.15,58.25 v10.15,55.08 10.15,31.58 BYP26.2 10.79,30.95 v10.79,33.49 | v6.34,58.89 6.34,76.03 5.71,76.67 BYP22.2 | BYP24.2 20.32,58.25 20.32,56.98 IC24.1 | v20.32,2.38 20.32,4.28 JP3.1 | v27.94,2.38 27.94,4.28 27.3,4.92 v27.3,27.77 | v63.49,30.31 63.49,32.22 IC20.10
  Bottom 0.508: v82.55,74.13 88.9,74.13 IC17.1 91.44,74.13 v101.59,74.13 | BYP28.2 108.58,48.73 109.22,48.73 IC28.8 | C1.1 112.39,71.59 111.12,71.59 C2.2 109.85,71.59 108.58,71.59 107.95,70.95 107.31,70.95 106.68,70.32 v101.59,70.32 | IC27.7 78.73,8.09 v81.28,8.09 82.55,6.82 88.9,6.82 90.17,5.55 92.07,5.55 C6.2 93.34,5.55 v100.33,5.55 104.77,5.55 BYP18.2 106.04,5.55 106.68,5.55 IC18.7 109.22,5.55 v110.48,5.55 | IC17.21 106.68,25.87 107.31,25.87 BYP19.2 108.58,25.87 109.22,25.87 IC19.8 111.76,25.87 v114.3,25.87 | v95.25,8.09 93.34,8.09 C4.2 | v46.98,66.51 41.27,66.51 IC22.14 | BYP20.2 48.89,20.79 50.16,20.79 C7.2 | IC20.10 63.49,34.76 62.86,35.39 51.43,35.39 50.79,34.76 IC20.15 | v55.88,43.65 v53.34,43.65 51.43,43.65 BYP21.2 50.16,43.65 v41.9,43.65 | v10.15,55.08 10.79,54.45 11.42,54.45 12.06,53.81 13.96,53.81 IC25.19 15.87,54.45 17.78,56.35 19.05,56.35 IC24.1 21.59,56.35 26.67,56.35 27.94,57.62 41.27,57.62 R13.1 | v6.34,58.89 9.52,58.89 BYP25.2 | IC26.10 8.25,4.92 10.79,4.92 11.42,4.28 20.32,4.28 JP3.1 | v10.79,33.49 8.88,33.49 IC25.10 6.34,33.49 5.71,33.49 SV9.10 4.44,33.49 3.17,33.49 SV9.9 | 22.22,27.77 21.59,27.14 16.51,27.14 15.87,26.5 IC26.19 | 22.22,27.77 22.22,29.68 10.79,29.68 10.15,30.31 BYP26.2 | v20.32,2.38 v27.94,2.38 | v27.3,27.77 22.22,27.77 | v63.49,30.31 v80.01,30.31
HLT\
  Top 0.254: IC17.2 90.8,72.22 92.07,73.5 92.07,75.4 91.44,76.03 91.44,77.3 92.7,78.58 R5.1
IO-E\  (via drill 0.61)
  Top 0.254: v69.84,18.88 v69.84,27.14 | v102.23,29.68 102.87,29.04 102.87,28.41 104.14,27.14 v112.39,27.14
  Bottom 0.254: v69.84,18.88 69.21,18.25 45.08,18.25 44.45,18.88 41.9,18.88 40,16.98 39.36,16.98 36.19,13.81 IC24.23 | v69.84,27.14 71.12,28.41 73.66,28.41 74.29,27.77 86.99,27.77 88.9,29.68 v102.23,29.68 | v112.39,27.14 114.3,27.14 115.56,25.87 116.84,25.87 IC19.9
IO-F\  (via drill 0.61)
  Top 0.254: v73.66,27.14 73.66,37.3 IC21.9
  Bottom 0.254: v73.66,27.14 107.31,27.14 108.58,28.41 109.22,28.41 IC19.7
IRQ\  (via drill 0.61)
  Top 0.254: IC24.38 35.55,50.63 35.55,49.37 IC24.37 | v45.71,51.27 45.08,51.91 45.08,57.62 44.45,58.25 v44.45,65.24 44.45,82.39 R7.1 | v87.62,69.05 87.62,67.78 88.9,66.51 IC17.4
  Bottom 0.254: v45.71,51.27 36.82,51.27 IC24.38 | v87.62,69.05 86.99,68.41 79.37,68.41 78.73,69.05 78.1,69.05 76.83,67.78 62.22,67.78 61.59,67.14 48.89,67.14 46.98,65.24 v44.45,65.24
MR
  Top 0.254: IC17.3 90.8,69.69 92.7,71.59 92.7,76.03 R8.1
N$3
  Top 0.254: IC17.39 106.04,72.22 107.31,73.5 107.31,74.13 109.85,76.67 C2.1
  Bottom 0.254: Q1.1 117.47,71.59 116.2,72.86 107.95,72.86 106.68,71.59 IC17.39
N$4
  Top 0.254: IC17.38 106.04,69.69 107.95,71.59 107.95,73.5 109.85,75.4 112.39,75.4 112.39,76.67 C1.2 113.66,76.67 117.47,76.67 Q1.2
N$5
  Bottom 0.254: IC25.2 8.88,53.81 10.15,52.54 17.78,52.54 19.05,53.81 IC24.2
N$6
  Top 0.254: IC18.5 107.31,11.27 107.31,12.54 IC18.4 107.31,13.81 107.31,15.08 IC18.3
N$21
  Top 0.254: IC18.1 106.68,20.79 106.04,20.79 R1.1 105.41,20.15 104.14,18.88 104.14,17.61 100.33,13.81 C3.1
N$22
  Top 0.254: IC18.2 106.68,18.25 106.04,18.25 R2.1 105.41,17.61 104.14,16.34 104.14,4.28 104.77,3.64 JP1.2
N$23  (via drill 0.61)
  Top 0.254: 59.68,37.94 59.05,37.94 IC21.3 | 59.68,37.94 60.32,37.94 IC21.4 | v73.02,19.52 v73.02,13.17 | v59.68,19.52 59.68,37.94
  Bottom 0.254: v73.02,13.17 76.2,13.17 IC27.5 | v73.02,19.52 72.39,20.15 60.32,20.15 v59.68,19.52
N$24
  Top 0.254: IC26.2 8.25,26.5 12.06,30.31 12.06,55.71 13.96,57.62 13.96,59.52 14.6,60.16 22.22,60.16 22.22,35.39 20.95,34.12 IC24.10
N$25  (via drill 0.61)
  Top 0.254: v3.81,7.46 3.81,21.42 4.44,22.06 5.71,22.06 6.34,22.7 6.34,23.33 IC26.3 | v11.42,6.82 v11.42,3.01 | v26.67,3.64 26.67,19.52 22.22,23.96 22.22,30.31 21.59,30.95 IC24.11
  Bottom 0.254: v3.81,7.46 4.44,6.82 v11.42,6.82 | v11.42,3.01 12.06,3.64 v26.67,3.64
N$27
  Top 0.254: IC27.6 76.83,11.27 74.93,13.17 74.93,16.98 R11.A
  Bottom 0.254: IC27.2 76.83,20.15 75.56,18.88 R11.A | C6.1 86.99,5.55 85.72,4.28 80.64,4.28 78.1,6.82 76.2,6.82 75.56,7.46 75.56,10.63 76.2,10.63 IC27.6
N$28
  Top 0.254: IC27.1 78.1,22.7 79.37,21.42 79.37,6.82 78.1,5.55 R9.1
  Bottom 0.254: R9.1 78.1,5.55 80.64,3.01 84.45,3.01 R10.2
N$94  (via drill 0.61)
  Top 0.254: v24.12,23.33 22.86,24.6 22.86,30.95 21.59,32.22 19.05,32.22 18.41,31.58 18.41,29.04 19.05,28.41 IC24.12
  Bottom 0.254: v24.12,23.33 22.86,22.06 12.69,22.06 11.42,20.79 8.88,20.79 IC26.4
N$124  (via drill 0.61)
  Top 0.254: v18.41,19.52 18.41,21.42 19.05,22.06 18.41,22.7 18.41,25.23 19.05,25.87 IC24.13
  Bottom 0.254: v18.41,19.52 8.88,19.52 8.25,18.88 IC26.5
N$125  (via drill 0.61)
  Top 0.254: v22.22,14.44 22.22,22.7 21.59,23.33 IC24.14
  Bottom 0.254: v22.22,14.44 13.96,14.44 13.33,15.08 10.79,15.08 10.15,15.71 8.88,15.71 IC26.6
N$126
  Bottom 0.254: IC26.7 8.88,13.17 10.15,11.9 22.86,11.9 26.67,15.71 26.67,19.52 22.86,19.52 21.59,20.79 IC24.15
N$127  (via drill 0.61)
  Top 0.254: v11.42,10.63 v11.42,16.98
  Bottom 0.254: v11.42,10.63 8.88,10.63 IC26.8 | v11.42,16.98 16.51,16.98 17.78,18.25 19.05,18.25 IC24.16
N$128  (via drill 0.61)
  Top 0.254: v25.39,9.36 v25.39,15.71
  Bottom 0.254: v25.39,9.36 8.88,9.36 8.25,8.73 IC26.9 | v25.39,15.71 21.59,15.71 IC24.17
N$129
  Bottom 0.254: IC25.3 8.88,51.27 10.15,50 17.78,50 19.05,51.27 IC24.3
N$130
  Bottom 0.254: IC25.4 8.88,48.73 9.52,48.09 13.33,48.09 13.96,47.46 17.78,47.46 19.05,48.73 IC24.4
N$131
  Bottom 0.254: IC25.5 8.88,46.19 9.52,45.55 13.33,45.55 13.96,44.92 17.78,44.92 19.05,46.19 IC24.5
N$132
  Bottom 0.254: IC25.6 8.88,43.65 10.15,42.38 17.78,42.38 19.05,43.65 IC24.6
N$133
  Bottom 0.254: IC25.7 8.88,41.11 9.52,40.48 13.33,40.48 13.96,39.84 17.78,39.84 19.05,41.11 IC24.7
N$134
  Bottom 0.254: IC25.8 8.88,38.57 9.52,37.94 13.33,37.94 13.96,37.3 17.78,37.3 19.05,38.57 IC24.8
N$135
  Bottom 0.254: IC25.9 8.88,36.03 9.52,35.39 13.33,35.39 13.96,34.76 17.78,34.76 19.05,36.03 IC24.9
N$136  (via drill 0.61)
  Top 0.254: v8.88,63.97 8.88,58.25 9.52,57.62 9.52,55.71 8.88,55.08 9.52,54.45 9.52,32.22 8.88,31.58 8.88,28.41 IC26.1 | v31.75,63.34 32.38,62.7 32.38,39.84 31.11,38.57 v31.11,11.9
  Bottom 0.254: v8.88,63.97 10.15,63.97 10.79,63.34 v31.75,63.34 | v31.11,11.9 29.84,10.63 21.59,10.63 IC24.19
N$137  (via drill 0.61)
  Top 0.254: v11.42,56.35 v11.42,61.43 | v23.49,61.43 v23.49,53.81
  Bottom 0.254: v11.42,56.35 8.88,56.35 IC25.1 | v11.42,61.43 12.06,62.06 22.86,62.06 v23.49,61.43 | v23.49,53.81 34.28,53.81 IC24.39
N$138
  Bottom 0.254: IC24.40 36.19,55.71 37.46,54.45 37.46,52.54 27.94,52.54 26.03,50.63 26.03,29.04 27.3,29.04 28.57,27.77 28.57,22.7 26.03,22.7 24.76,21.42 24.76,20.15 27.3,20.15 33.65,13.81 33.65,11.9 40,11.9 40.63,11.27 69.84,11.27 73.02,14.44 80.01,14.44 83.81,10.63 IC27.9
N$140
  Top 0.254: IC27.8 86.36,8.09 86.99,8.09 C4.1 87.62,8.73 88.9,10 88.9,14.44 85.72,17.61 IC27.12
  Bottom 0.254: R4.1 92.07,10.63 89.53,8.09 88.26,8.09 C4.1
N$141
  Top 0.254: R3.1 90.8,18.25 92.07,18.25 R4.2
  Bottom 0.254: IC27.13 86.36,20.79 87.62,19.52 88.26,19.52 89.53,18.25 R3.1
N$142
  Bottom 0.254: IC27.11 86.36,15.71 94.61,15.71 C5.1
N$143
  Top 0.254: R10.1 76.83,3.01 75.56,4.28 75.56,4.92 R11.E
N$144
  Bottom 0.254: X1.4 52.06,15.08 52.7,14.44 57.78,14.44 58.41,13.81 X1.6
N$145
  Top 0.254: X1.8 53.97,13.17 55.24,13.17 X1.7
N$146
  Top 0.254: X1.5 48.89,15.08 44.45,15.08 X1.G2
  Bottom 0.254: X1.G1 64.77,15.08 62.86,16.98 50.16,16.98 49.52,16.34 X1.5
N$147
  Top 0.254: IC18.12 114.93,16.34 114.93,17.61 IC18.13
  Bottom 0.254: IC21.5 62.86,37.94 61.59,36.66 45.08,36.66 41.9,33.49 41.9,32.22 44.45,29.68 44.45,19.52 58.41,19.52 59.68,20.79 74.93,20.79 76.2,22.06 110.48,22.06 114.3,18.25 IC18.13
N$148
  Top 0.254: LED1.K 118.11,11.27 116.84,12.54 116.84,13.17 IC18.11
N$149
  Bottom 0.254: R12.1 88.26,18.25 89.53,16.98 120.65,16.98 125.73,11.9 125.73,10.63 121.28,10.63 LED1.A
N$150
  Top 0.254: IC21.24 53.34,55.08 53.34,56.35 JP2.1
  Bottom 0.254: R13.2 50.16,57.62 52.7,57.62 JP2.1
N$151
  Top 0.254: IC18.8 116.2,6.18 119.38,9.36 119.38,24.6 120.01,25.23 120.01,44.28 116.2,48.09 116.2,64.61 116.84,65.24 114.3,67.78 114.3,72.22 113.66,72.86 108.58,72.86 108.58,60.8 109.85,59.52 IC28.4
N$152
  Bottom 0.254: IC19.5 111.12,34.12 114.3,37.3 114.3,44.92 116.84,44.92 120.01,48.09 120.01,63.34 118.74,63.34 IC28.15
N$153
  Top 0.254: IC20.7 64.13,25.23 65.4,25.23 IC20.8
N$154
  Top 0.254: C7.1 55.88,20.15 55.88,15.08 56.51,14.44 64.13,14.44 64.13,16.34 65.4,17.61 71.75,17.61 71.75,19.52 73.02,20.79 75.56,20.79 75.56,20.15 76.83,18.88 IC27.3
N$155
  Top 0.254: IC20.5 58.41,24.6 58.41,19.52 59.68,18.25 67.31,18.25 67.31,31.58 68.58,32.85 C9.2
N$156
  Bottom 0.254: IC20.4 56.51,26.5 58.41,28.41 67.94,28.41 C9.1
N$157
  Bottom 0.254: C8.2 45.71,30.31 45.71,27.77 51.43,27.77 52.7,26.5 IC20.3
N$158
  Top 0.254: C8.1 46.35,25.87 47.62,25.87 IC20.1
N$159
  Bottom 0.254: C11.1 56.51,23.33 57.14,23.96 59.05,23.96 60.32,25.23 IC20.6
N$160
  Bottom 0.254: C10.2 48.89,23.33 50.16,24.6 50.79,24.6 IC20.2
NMI\  (via drill 0.61)
  Top 0.254: IC17.6 88.9,61.43 88.26,61.43 R6.1 87.62,60.8 87.62,57.62 86.36,56.35 86.36,53.17 86.99,52.54 86.99,43.65 v86.36,43.02 | v68.58,42.38 68.58,39.84 IC21.7
  Bottom 0.254: v68.58,42.38 69.21,41.74 80.01,41.74 81.28,43.02 v86.36,43.02
PIA-A0  (via drill 0.61)
  Top 0.254: v2.54,52.54 2.54,44.28 SV9.1
  Bottom 0.254: v2.54,52.54 8.88,52.54 9.52,51.91 11.42,51.91 12.06,51.27 13.96,51.27 IC25.18
PIA-A1  (via drill 0.61)
  Top 0.254: v5.08,50 5.08,44.28 SV9.2
  Bottom 0.254: v5.08,50 8.88,50 9.52,49.37 11.42,49.37 12.06,48.73 13.96,48.73 IC25.17
PIA-A2
  Bottom 0.254: IC25.16 13.96,46.19 12.69,47.46 4.44,47.46 1.27,44.28 1.27,41.74 2.54,41.74 SV9.3
PIA-A3
  Bottom 0.254: IC25.15 13.96,43.65 12.69,44.92 4.44,44.92 3.81,44.28 3.81,41.74 5.08,41.74 SV9.4
PIA-A4  (via drill 0.61)
  Top 0.254: v13.33,32.22 13.33,40.48 13.96,41.11 IC25.14 | v3.81,32.22 3.81,36.66 3.17,37.3 3.17,38.57 SV9.5
  Bottom 0.254: v3.81,32.22 v13.33,32.22
PIA-A5
  Bottom 0.254: IC25.13 13.96,38.57 12.69,39.84 5.71,39.84 5.08,39.2 SV9.6
PIA-A6
  Bottom 0.254: IC25.12 13.96,36.03 12.69,37.3 4.44,37.3 3.17,36.03 SV9.7
PIA-A7
  Bottom 0.254: IC25.11 13.96,33.49 12.69,34.76 5.71,34.76 5.08,35.39 SV9.8
PIA-B0
  Bottom 0.254: IC26.18 13.96,23.33 12.69,24.6 4.44,24.6 3.81,25.23 3.81,27.77 2.54,27.77 SV9.13
PIA-B1  (via drill 0.61)
  Top 0.254: v13.33,27.14 13.33,21.42 13.96,20.79 IC26.17
  Bottom 0.254: v13.33,27.14 5.71,27.14 5.08,27.77 SV9.14
PIA-B2  (via drill 0.61)
  Top 0.254: v17.78,57.62 17.78,31.58 17.14,30.95 17.14,18.88 16.51,18.25 IC26.16 | v2.54,57.62 1.27,56.35 1.27,40.48 1.9,39.84 v3.81,39.84
  Bottom 0.254: v2.54,57.62 v17.78,57.62 | v3.81,39.84 1.9,39.84 1.27,39.2 1.27,25.87 1.9,25.87 SV9.15
PIA-B3  (via drill 0.61)
  Top 0.254: v2.54,16.98 1.27,18.25 1.27,22.06 3.17,22.06 3.81,22.7 3.81,23.96 4.44,24.6 4.44,25.87 SV9.16
  Bottom 0.254: v2.54,16.98 8.88,16.98 9.52,16.34 10.79,16.34 11.42,15.71 13.96,15.71 IC26.15
PIA-B4
  Bottom 0.254: IC26.14 13.96,13.17 12.69,14.44 3.81,14.44 1.27,16.98 1.27,23.33 1.9,23.33 SV9.17
PIA-B5  (via drill 0.61)
  Top 0.254: v12.69,10.63 11.42,9.36 10.79,9.36 10.79,10 10.15,10.63 10.79,11.27 10.79,16.34 10.15,16.98 10.15,18.25 10.79,18.88 v10.79,22.06
  Bottom 0.254: v12.69,10.63 13.96,10.63 IC26.13 | v10.79,22.06 6.34,22.06 5.71,22.7 5.08,22.7 SV9.18
PIA-B6  (via drill 0.61)
  Top 0.254: v10.15,8.09 10.15,9.36 9.52,10 9.52,11.27 8.88,11.9 5.08,11.9 5.08,13.81 4.44,14.44 4.44,15.08 5.08,15.71 v5.08,18.25 | v2.54,18.25 2.54,20.15 SV9.19
  Bottom 0.254: v10.15,8.09 13.96,8.09 IC26.12 | v5.08,18.25 v2.54,18.25
PIA-B7
  Top 0.254: IC26.11 14.6,6.18 13.33,7.46 13.33,8.73 13.96,9.36 17.14,9.36 17.14,11.27 16.51,11.9 12.69,11.9 12.69,21.42 10.79,23.33 9.52,23.33 9.52,20.15 8.88,19.52 5.08,19.52 5.08,20.15 SV9.20
R/W\  (via drill 0.61)
  Top 0.254: v81.28,41.74 81.28,52.54 IC21.13 81.28,55.08 v81.28,57.62 | IC24.21 36.82,8.09 36.82,9.36 38.09,10.63 38.09,19.52 39.36,20.79 v39.36,41.11 38.73,41.74 38.73,64.61 39.36,65.24 v39.36,69.69 | v10.15,69.05 10.15,80.48 IC22.27
  Bottom 0.254: v39.36,41.11 80.64,41.11 v81.28,41.74 | v10.15,69.05 38.73,69.05 v39.36,69.69 | v81.28,57.62 91.44,57.62 92.7,58.89 104.14,58.89 IC17.34
RST\  (via drill 0.61)
  Top 0.254: v32.38,37.3 31.75,36.66 31.75,12.54 32.38,11.9 v32.38,2.38 | v102.87,2.38 v102.87,8.09 | v123.19,74.77 123.19,63.97 124.45,62.7 124.45,36.03 123.19,34.76 v123.19,9.36
  Bottom 0.254: v32.38,37.3 31.11,37.3 31.11,38.57 32.38,39.84 34.28,39.84 34.92,40.48 IC24.34 | v32.38,2.38 33.02,1.74 102.23,1.74 v102.87,2.38 | v102.87,8.09 106.68,8.09 IC18.6 109.22,8.09 111.12,8.09 112.39,9.36 v123.19,9.36 | v123.19,74.77 110.48,74.77 109.85,74.13 106.68,74.13 IC17.40
RX
  Top 0.254: IC20.12 58.41,34.76 55.88,37.3 IC21.2
RXD
  Top 0.254: IC20.13 55.88,32.22 57.14,30.95 57.14,16.34 X1.2
TX
  Bottom 0.254: IC20.11 60.32,32.85 59.05,31.58 50.16,31.58 49.52,32.22 49.52,36.03 63.49,36.03 65.4,37.94 IC21.6
TXD
  Top 0.254: IC20.14 53.34,32.22 54.6,30.95 54.6,16.34 X1.3
VCC  (via drill 0.61)
  Top 0.508: BYP20.1 43.17,21.42 43.17,22.7 C10.1 43.17,23.96 v43.17,33.49 | v48.25,38.57 48.25,34.76 IC20.16 | v17.78,8.09 17.78,6.18 R14.2 | 37.46,15.08 37.46,11.27 36.82,10.63 IC24.22 | 37.46,15.08 36.82,15.71 IC24.24 | v38.09,20.79 37.46,20.15 37.46,15.08 | v97.79,10.63 97.79,17.61 R2.2 97.79,18.88 97.79,20.15 R1.2 97.79,21.42 v97.79,23.33 | IC27.14 85.09,23.96 85.09,25.23 BYP27.1 85.09,26.5 v85.09,38.57 | v82.55,5.55 v82.55,13.17 81.91,13.81 v81.91,15.71 v81.91,23.33 | v87.62,13.17 87.62,11.27 R12.2 | IC26.20 15.23,29.04 15.23,30.31 BYP26.1 15.87,30.95 17.14,32.22 17.14,55.71 16.51,56.35 IC25.20 15.23,56.98 15.23,58.25 BYP25.1 | IC22.28 7.62,80.48 7.62,67.78 IC22.1 7.62,65.24 v7.62,60.16 | IC23.28 49.52,79.21 49.52,66.51 IC23.1 49.52,63.97 v49.52,61.43 | R7.2 52.06,82.39 52.06,81.75 IC23.27 | v55.88,61.43 55.88,58.89 JP2.2 | IC18.14 115.56,21.42 v115.56,29.68 v115.56,43.65 114.3,44.92 v114.3,53.81 v114.3,66.51 | v87.62,56.35 87.62,54.45 R6.2 87.62,53.17 v87.62,39.84 | R5.2 100.33,78.58 100.33,77.3 R8.2 100.33,76.03 v100.33,63.97 v100.33,56.35 | IC17.36 105.41,63.34 105.41,62.06 IC17.35 106.68,61.43 107.95,60.16 107.95,54.45 BYP28.1 | v25.39,61.43 25.39,59.52 BYP24.1
  Bottom 0.508: v48.25,38.57 50.16,38.57 BYP21.1 50.79,39.2 52.06,40.48 71.75,40.48 | v43.17,33.49 47.62,33.49 IC20.16 | v17.78,8.09 19.05,8.09 IC24.20 21.59,8.09 28.57,8.09 31.11,10.63 34.28,10.63 IC24.22 | v38.09,20.79 42.54,20.79 BYP20.1 | v97.79,10.63 104.77,10.63 BYP18.1 | BYP17.1 99.69,23.33 v97.79,23.33 86.36,23.33 IC27.14 83.81,23.33 v81.91,23.33 | 71.75,40.48 71.12,39.84 IC21.8 | 71.75,40.48 75.56,40.48 | 75.56,40.48 76.2,39.84 IC21.10 | 81.28,39.84 80.64,40.48 75.56,40.48 | 81.28,39.84 IC21.12 | R12.2 88.26,10.63 89.53,10.63 R3.2 | v82.55,5.55 84.45,5.55 R9.2 | v82.55,13.17 83.81,13.17 IC27.10 86.36,13.17 v87.62,13.17 | v81.91,15.71 78.73,15.71 IC27.4 | v85.09,38.57 81.91,38.57 IC21.12 | SV9.11 3.17,30.95 4.44,30.95 SV9.12 5.71,30.95 6.34,30.95 6.98,30.31 8.88,30.31 10.79,28.41 13.96,28.41 IC26.20 | BYP24.1 25.39,59.52 24.76,60.16 18.41,60.16 17.14,58.89 15.87,58.89 BYP25.1 15.23,59.52 14.6,60.16 v7.62,60.16 | BYP22.1 5.71,81.75 6.98,81.75 IC22.28 | BYP23.1 47.62,80.48 48.89,80.48 IC23.28 50.16,80.48 51.43,80.48 IC23.27 | v55.88,61.43 v49.52,61.43 v25.39,61.43 | v115.56,43.65 116.84,43.65 IC19.16 | v115.56,29.68 108.58,29.68 107.95,30.31 BYP19.1 | BYP28.1 108.58,53.81 109.22,53.81 IC28.6 111.76,53.81 v114.3,53.81 | v114.3,66.51 116.84,66.51 IC28.16 | v100.33,63.97 104.14,63.97 IC17.36 | v100.33,56.35 91.44,56.35 IC17.8 88.9,56.35 v87.62,56.35 55.88,56.35 JP2.2 | 81.28,39.84 v87.62,39.84 | 81.28,39.84 IC21.12
VMA  (via drill 0.61)
  Top 0.254: v112.39,8.09 111.76,8.73 111.76,23.33 v112.39,23.96 | v96.52,24.6 96.52,33.49 95.25,34.76 95.25,60.16 v95.88,60.8
  Bottom 0.254: v112.39,8.09 114.3,8.09 IC18.9 | v112.39,23.96 106.68,23.96 106.04,24.6 v96.52,24.6 | v95.88,60.8 92.7,63.97 91.44,63.97 IC17.5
